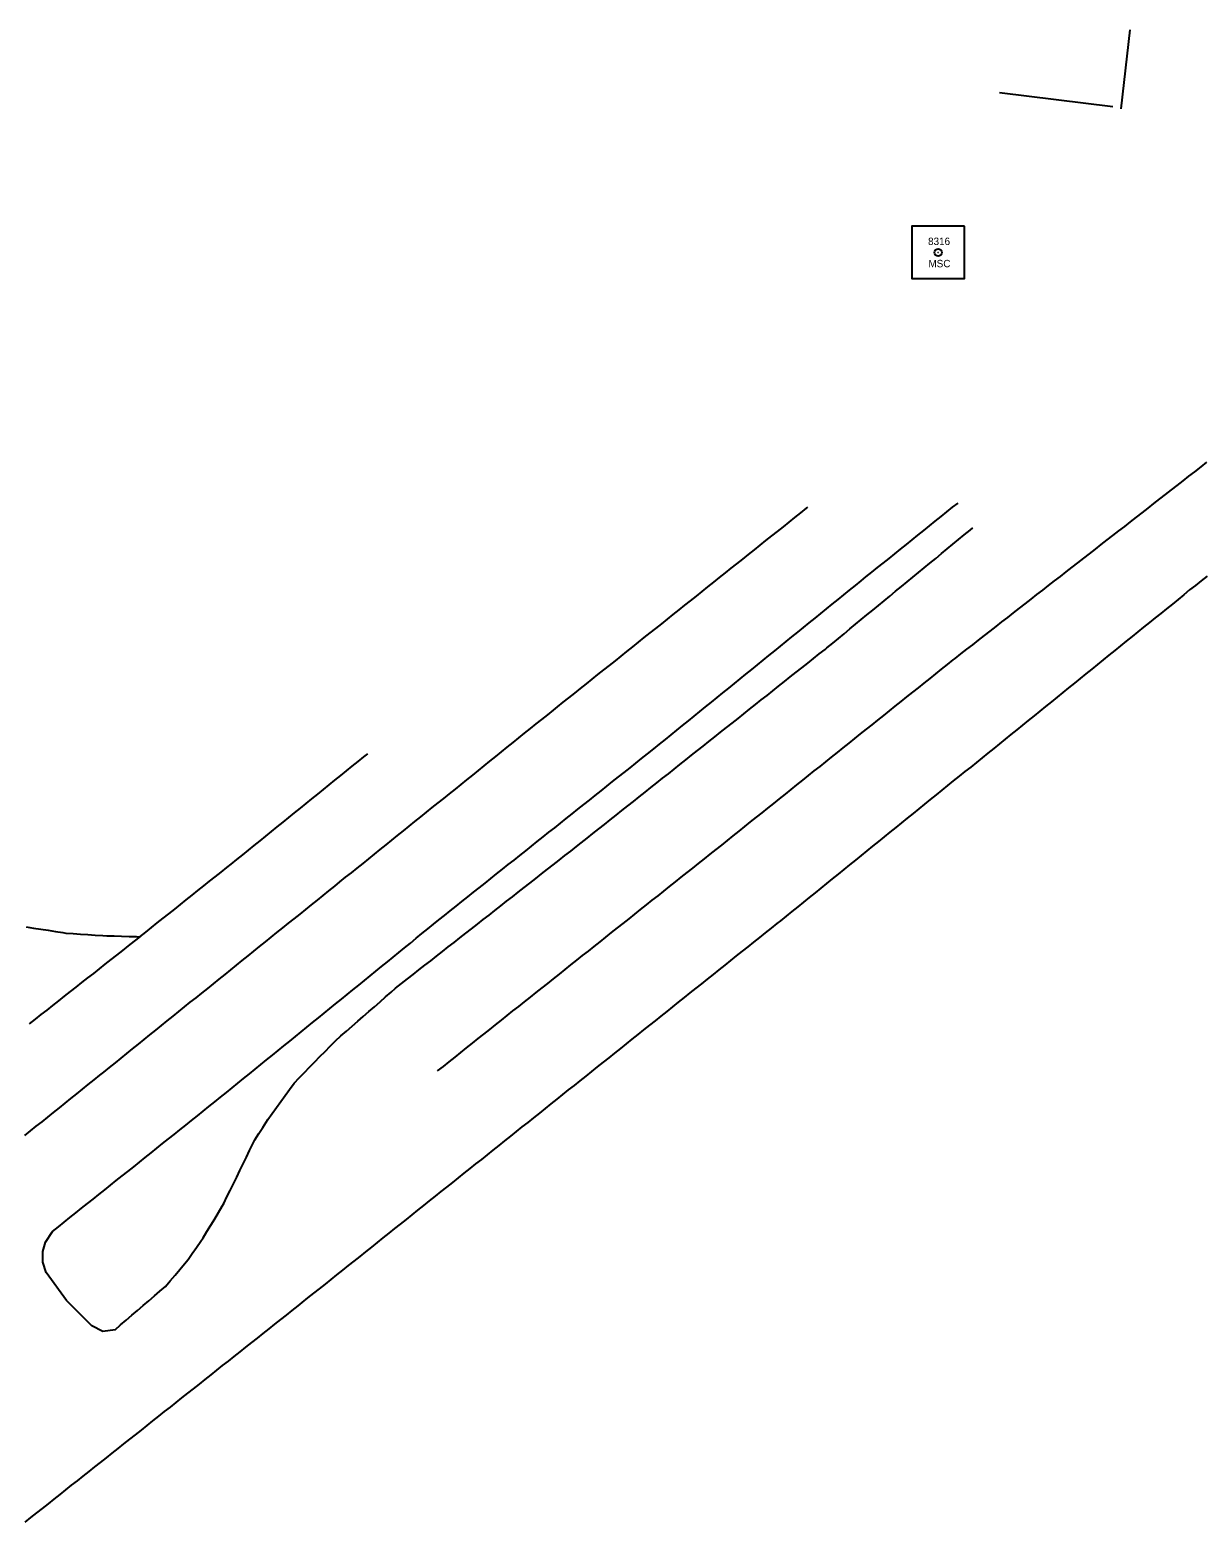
# Model space of a CAD drawing. Extents: x 205929 to 2357175, y -1785700 to 846739.
# Drawn here: x 2022787.1 to 2022945.3, y 806798.9 to 807000.3 of the extents above; entities that cross this region are included whole.
import ezdxf

# ---------------------------------------------------------------- set-up
doc = ezdxf.new("R2010")
doc.units = 0
for name, color, linetype in [('RD_HC_Survey', 7, 'Continuous'), ('RD_HC_txCode', 7, 'Continuous'), ('RD_Sketch1', 7, 'Continuous'), ('RD_SMD_Locator', 7, 'Continuous')]:
    doc.layers.add(name, color=color, linetype=linetype)

msp = doc.modelspace()

# ---------------------------------------------------------------- linework, layer by layer
at = {"layer": 'RD_HC_Survey'}
msp.add_lwpolyline([(2022913.2, 806973.76), (2022906.13, 806973.76), (2022906.13, 806966.69), (2022913.2, 806966.69)], close=True, dxfattribs=at)
msp.add_circle((2022909.67, 806970.22), 0.5, dxfattribs=at)
at = {"layer": 'RD_Sketch1'}
for points in [[(2022935.52, 807000.26), (2022934.33, 806989.6)], [(2022917.94, 806991.81), (2022933.23, 806989.93)], [(2022842.12, 806859.77), (2022842.9, 806860.39), (2022843.68, 806861.01), (2022844.47, 806861.64), (2022845.25, 806862.26), (2022846.03, 806862.88), (2022846.81, 806863.5), (2022847.6, 806864.13), (2022848.38, 806864.75), (2022849.16, 806865.37), (2022849.95, 806865.99), (2022850.73, 806866.62), (2022851.51, 806867.24), (2022852.29, 806867.86), (2022853.08, 806868.48), (2022853.86, 806869.1), (2022854.64, 806869.73), (2022855.42, 806870.35), (2022856.21, 806870.97), (2022856.99, 806871.59), (2022857.77, 806872.22), (2022858.56, 806872.84), (2022859.34, 806873.46), (2022860.12, 806874.08), (2022860.9, 806874.71), (2022861.69, 806875.33), (2022862.47, 806875.95), (2022863.25, 806876.57), (2022864.04, 806877.19), (2022864.82, 806877.82), (2022865.6, 806878.44), (2022866.38, 806879.06), (2022867.17, 806879.68), (2022867.95, 806880.31), (2022868.73, 806880.93), (2022869.51, 806881.55), (2022870.3, 806882.17), (2022871.08, 806882.8), (2022871.86, 806883.42), (2022872.65, 806884.04), (2022873.43, 806884.66), (2022874.21, 806885.28), (2022874.99, 806885.91), (2022875.78, 806886.53), (2022876.56, 806887.15), (2022877.34, 806887.77), (2022878.12, 806888.4), (2022878.91, 806889.02), (2022879.69, 806889.64), (2022880.46, 806890.25), (2022881.24, 806890.88), (2022882.02, 806891.5), (2022882.8, 806892.13), (2022883.58, 806892.75), (2022884.36, 806893.37), (2022885.14, 806894), (2022885.92, 806894.62), (2022886.7, 806895.25), (2022887.49, 806895.87), (2022888.27, 806896.5), (2022889.05, 806897.12), (2022889.83, 806897.75), (2022890.61, 806898.37), (2022891.39, 806899), (2022892.17, 806899.62), (2022892.17, 806899.62), (2022892.95, 806900.25), (2022893.73, 806900.87), (2022894.51, 806901.5), (2022895.29, 806902.12), (2022896.07, 806902.74), (2022896.86, 806903.37), (2022897.64, 806903.99), (2022898.42, 806904.62), (2022899.2, 806905.24), (2022899.98, 806905.87), (2022900.76, 806906.49), (2022901.54, 806907.12), (2022902.32, 806907.74), (2022903.1, 806908.37), (2022903.88, 806908.99), (2022904.66, 806909.62), (2022905.45, 806910.24), (2022906.23, 806910.87), (2022907.01, 806911.49), (2022907.79, 806912.11), (2022908.57, 806912.74), (2022909.35, 806913.36), (2022910.13, 806913.99), (2022910.91, 806914.61), (2022911.69, 806915.24), (2022911.95, 806915.44), (2022912.74, 806916.06), (2022913.53, 806916.67), (2022914.32, 806917.29), (2022915.11, 806917.9), (2022915.9, 806918.52), (2022916.68, 806919.13), (2022917.47, 806919.74), (2022918.26, 806920.36), (2022919.05, 806920.97), (2022919.84, 806921.59), (2022920.63, 806922.2), (2022921.42, 806922.82), (2022922.21, 806923.43), (2022923, 806924.05), (2022923.79, 806924.66), (2022924.57, 806925.27), (2022925.36, 806925.89), (2022926.15, 806926.5), (2022926.94, 806927.12), (2022927.73, 806927.73), (2022928.52, 806928.35), (2022929.31, 806928.96), (2022930.1, 806929.57), (2022930.89, 806930.19), (2022931.68, 806930.8), (2022932.46, 806931.42), (2022933.25, 806932.03), (2022934.04, 806932.65), (2022934.83, 806933.26), (2022935.62, 806933.88), (2022936.41, 806934.49), (2022937.2, 806935.1), (2022937.99, 806935.72), (2022938.78, 806936.33), (2022939.57, 806936.95), (2022940.35, 806937.56), (2022941.14, 806938.18), (2022941.93, 806938.79), (2022941.93, 806938.79), (2022942.72, 806939.4), (2022943.51, 806940.02), (2022944.3, 806940.63), (2022945.13, 806941.28), (2022945.9, 806941.9)], [(2022892.04, 806935.85), (2022891.85, 806935.7), (2022891.07, 806935.08), (2022890.29, 806934.45), (2022889.51, 806933.83), (2022888.73, 806933.21), (2022887.94, 806932.58), (2022887.16, 806931.96), (2022886.38, 806931.34), (2022885.6, 806930.71), (2022884.82, 806930.09), (2022884.04, 806929.47), (2022883.25, 806928.84), (2022882.47, 806928.22), (2022881.69, 806927.6), (2022880.91, 806926.97), (2022880.13, 806926.35), (2022879.35, 806925.73), (2022878.56, 806925.1), (2022877.78, 806924.48), (2022877, 806923.86), (2022876.22, 806923.23), (2022875.44, 806922.61), (2022874.66, 806921.99), (2022873.87, 806921.36), (2022873.09, 806920.74), (2022872.31, 806920.11), (2022871.53, 806919.49), (2022870.75, 806918.87), (2022869.97, 806918.24), (2022869.18, 806917.62), (2022868.4, 806917), (2022867.62, 806916.37), (2022866.84, 806915.75), (2022866.06, 806915.13), (2022865.28, 806914.5), (2022864.49, 806913.88), (2022863.71, 806913.26), (2022862.93, 806912.63), (2022862.15, 806912.01), (2022861.37, 806911.39), (2022860.59, 806910.76), (2022859.8, 806910.14), (2022859.02, 806909.52), (2022858.24, 806908.89), (2022857.71, 806908.47), (2022856.93, 806907.84), (2022856.15, 806907.21), (2022856.15, 806907.21), (2022855.37, 806906.59), (2022854.6, 806905.96), (2022853.82, 806905.33), (2022853.04, 806904.71), (2022852.26, 806904.08), (2022851.48, 806903.45), (2022850.7, 806902.82), (2022849.92, 806902.2), (2022849.14, 806901.57), (2022848.36, 806900.94), (2022847.58, 806900.32), (2022846.81, 806899.69), (2022846.03, 806899.06), (2022845.25, 806898.44), (2022844.47, 806897.81), (2022843.69, 806897.18), (2022842.91, 806896.55), (2022842.13, 806895.93), (2022841.35, 806895.3), (2022840.57, 806894.67), (2022839.8, 806894.05), (2022839.02, 806893.42), (2022838.24, 806892.79), (2022837.46, 806892.17), (2022836.68, 806891.54), (2022835.9, 806890.91), (2022835.12, 806890.28), (2022834.34, 806889.66), (2022833.56, 806889.03), (2022832.79, 806888.4), (2022832.01, 806887.78), (2022831.23, 806887.15), (2022830.45, 806886.52), (2022829.67, 806885.9), (2022828.89, 806885.27), (2022828.19, 806884.7), (2022827.41, 806884.08), (2022826.63, 806883.45), (2022825.85, 806882.82), (2022825.07, 806882.19), (2022824.29, 806881.57), (2022823.51, 806880.94), (2022822.73, 806880.31), (2022821.96, 806879.69), (2022821.18, 806879.06), (2022820.4, 806878.43), (2022819.62, 806877.81), (2022818.84, 806877.18), (2022818.06, 806876.55), (2022817.28, 806875.92), (2022816.5, 806875.3), (2022815.72, 806874.67), (2022814.94, 806874.04), (2022814.17, 806873.42), (2022813.39, 806872.79), (2022812.61, 806872.16), (2022811.83, 806871.54), (2022811.05, 806870.91), (2022810.27, 806870.28), (2022809.49, 806869.65), (2022808.71, 806869.03), (2022807.93, 806868.4), (2022807.15, 806867.77), (2022806.38, 806867.15), (2022806.38, 806867.15), (2022805.6, 806866.52), (2022804.82, 806865.89), (2022804.04, 806865.27), (2022803.26, 806864.64), (2022802.48, 806864.01), (2022801.7, 806863.38), (2022800.92, 806862.76), (2022800.14, 806862.13), (2022799.36, 806861.5), (2022798.59, 806860.88), (2022797.81, 806860.25), (2022797.03, 806859.62), (2022796.49, 806859.19), (2022795.72, 806858.57), (2022794.94, 806857.94), (2022794.16, 806857.31), (2022793.38, 806856.69), (2022792.6, 806856.06), (2022791.82, 806855.43), (2022791.04, 806854.8), (2022790.26, 806854.18), (2022789.48, 806853.55), (2022788.71, 806852.92), (2022787.93, 806852.3), (2022787.15, 806851.67), (2022786.37, 806851.04)], [(2022790.17, 806838.11), (2022790.95, 806838.74), (2022791.73, 806839.36), (2022792.51, 806839.98), (2022793.29, 806840.61), (2022794.07, 806841.23), (2022794.86, 806841.86), (2022795.64, 806842.48), (2022796.42, 806843.1), (2022797.2, 806843.73), (2022797.98, 806844.35), (2022798.76, 806844.98), (2022799.54, 806845.6), (2022800.33, 806846.22), (2022801.11, 806846.85), (2022801.89, 806847.47), (2022802.67, 806848.1), (2022803.45, 806848.72), (2022804.23, 806849.34), (2022805.01, 806849.97), (2022805.8, 806850.59), (2022806.58, 806851.21), (2022807.36, 806851.84), (2022808.14, 806852.46), (2022808.92, 806853.09), (2022809.7, 806853.71), (2022810.49, 806854.33), (2022811.27, 806854.96), (2022812.05, 806855.58), (2022812.84, 806856.22), (2022813.62, 806856.85), (2022814.4, 806857.48), (2022815.17, 806858.11), (2022815.95, 806858.74), (2022816.72, 806859.37), (2022817.5, 806860), (2022818.28, 806860.63), (2022819.05, 806861.26), (2022819.83, 806861.9), (2022820.6, 806862.53), (2022821.38, 806863.16), (2022822.16, 806863.79), (2022822.93, 806864.42), (2022823.71, 806865.05), (2022824.48, 806865.68), (2022825.26, 806866.31), (2022826.03, 806866.94), (2022826.81, 806867.57), (2022827.59, 806868.2), (2022828.36, 806868.83), (2022829.14, 806869.46), (2022829.91, 806870.1), (2022830.69, 806870.73), (2022831.47, 806871.36), (2022832.24, 806871.99), (2022833.02, 806872.62), (2022833.79, 806873.25), (2022834.57, 806873.88), (2022835.35, 806874.51), (2022836.12, 806875.14), (2022836.9, 806875.77), (2022837.67, 806876.4), (2022838.45, 806877.03), (2022839.23, 806877.67), (2022840, 806878.3), (2022840, 806878.3), (2022840.78, 806878.93), (2022841.55, 806879.56), (2022842.27, 806880.14), (2022843.05, 806880.76), (2022843.83, 806881.38), (2022844.62, 806882.01), (2022845.4, 806882.63), (2022846.18, 806883.25), (2022846.96, 806883.88), (2022847.75, 806884.5), (2022848.53, 806885.12), (2022849.31, 806885.74), (2022850.09, 806886.37), (2022850.88, 806886.99), (2022851.66, 806887.61), (2022852.44, 806888.23), (2022853.22, 806888.86), (2022854.01, 806889.48), (2022854.79, 806890.1), (2022855.57, 806890.72), (2022856.35, 806891.35), (2022857.14, 806891.97), (2022857.92, 806892.59), (2022858.7, 806893.22), (2022859.48, 806893.84), (2022860.26, 806894.46), (2022861.05, 806895.08), (2022861.83, 806895.71), (2022862.61, 806896.33), (2022863.39, 806896.95), (2022864.18, 806897.57), (2022864.96, 806898.2), (2022865.74, 806898.82), (2022866.52, 806899.44), (2022867.31, 806900.06), (2022868.09, 806900.69), (2022868.87, 806901.31), (2022869.65, 806901.93), (2022870.44, 806902.56), (2022871.3, 806903.24), (2022872.07, 806903.87), (2022872.85, 806904.5), (2022873.63, 806905.13), (2022874.4, 806905.76), (2022875.18, 806906.39), (2022875.96, 806907.02), (2022876.73, 806907.65), (2022877.51, 806908.28), (2022878.29, 806908.9), (2022879.07, 806909.53), (2022879.84, 806910.16), (2022880.62, 806910.79), (2022881.4, 806911.42), (2022882.17, 806912.05), (2022882.95, 806912.68), (2022883.73, 806913.31), (2022884.5, 806913.94), (2022885.28, 806914.57), (2022886.06, 806915.2), (2022886.83, 806915.83), (2022887.61, 806916.46), (2022888.39, 806917.09), (2022889.17, 806917.72), (2022889.94, 806918.35), (2022889.94, 806918.35), (2022890.72, 806918.98), (2022891.5, 806919.61), (2022892.27, 806920.24), (2022893.05, 806920.87), (2022893.83, 806921.5), (2022894.6, 806922.13), (2022895.38, 806922.76), (2022896.16, 806923.39), (2022896.93, 806924.01), (2022897.71, 806924.64), (2022898.49, 806925.27), (2022899.27, 806925.9), (2022899.92, 806926.43), (2022900.7, 806927.06), (2022901.48, 806927.69), (2022902.26, 806928.31), (2022903.04, 806928.94), (2022903.82, 806929.56), (2022904.6, 806930.19), (2022905.38, 806930.82), (2022906.16, 806931.44), (2022906.94, 806932.07), (2022907.72, 806932.7), (2022908.5, 806933.32), (2022909.28, 806933.95), (2022910.06, 806934.57), (2022910.84, 806935.2), (2022911.62, 806935.83), (2022912.35, 806936.41)], [(2022798.59, 806824.85), (2022799.34, 806825.5), (2022800.1, 806826.15), (2022800.86, 806826.8), (2022801.62, 806827.45), (2022802.38, 806828.1), (2022803.14, 806828.75), (2022803.9, 806829.4), (2022804.66, 806830.05), (2022805.4, 806830.68), (2022806.04, 806831.45), (2022806.69, 806832.22), (2022807.33, 806832.98), (2022807.97, 806833.75), (2022808.45, 806834.31), (2022809.02, 806835.13), (2022809.59, 806835.95), (2022810.16, 806836.78), (2022810.49, 806837.25), (2022811, 806838.11), (2022811.52, 806838.97), (2022812.04, 806839.82), (2022812.55, 806840.68), (2022813.07, 806841.54), (2022813.26, 806841.86), (2022813.7, 806842.76), (2022814.13, 806843.65), (2022814.57, 806844.55), (2022815.01, 806845.45), (2022815.45, 806846.35), (2022815.89, 806847.25), (2022816.32, 806848.15), (2022816.76, 806849.05), (2022817.2, 806849.95), (2022817.45, 806850.47), (2022817.99, 806851.31), (2022818.53, 806852.15), (2022819.21, 806853.22), (2022819.8, 806854.03), (2022820.38, 806854.84), (2022820.97, 806855.65), (2022821.55, 806856.46), (2022822.14, 806857.27), (2022822.75, 806858.12), (2022823.45, 806858.83), (2022824.15, 806859.55), (2022824.85, 806860.26), (2022825.54, 806860.98), (2022826.24, 806861.7), (2022826.94, 806862.41), (2022827.64, 806863.13), (2022828.33, 806863.83), (2022829.08, 806864.49), (2022829.83, 806865.15), (2022830.58, 806865.81), (2022831.34, 806866.47), (2022832.09, 806867.13), (2022832.84, 806867.78), (2022833.59, 806868.44), (2022834.35, 806869.1), (2022835.1, 806869.76), (2022835.85, 806870.42), (2022836.46, 806870.95), (2022837.25, 806871.57), (2022838.04, 806872.18), (2022838.04, 806872.18), (2022838.82, 806872.8), (2022839.61, 806873.42), (2022840.4, 806874.03), (2022841.19, 806874.65), (2022841.97, 806875.27), (2022842.76, 806875.88), (2022843.55, 806876.5), (2022844.34, 806877.11), (2022845.12, 806877.73), (2022845.91, 806878.35), (2022846.7, 806878.96), (2022847.49, 806879.58), (2022848.27, 806880.2), (2022849.06, 806880.81), (2022849.85, 806881.43), (2022850.64, 806882.04), (2022851.42, 806882.66), (2022852.21, 806883.28), (2022853, 806883.89), (2022853.79, 806884.51), (2022854.57, 806885.13), (2022855.36, 806885.74), (2022856.15, 806886.36), (2022856.93, 806886.98), (2022857.72, 806887.59), (2022858.51, 806888.21), (2022859.3, 806888.82), (2022860.08, 806889.44), (2022860.87, 806890.06), (2022861.51, 806890.55), (2022862.29, 806891.18), (2022863.07, 806891.8), (2022863.86, 806892.42), (2022864.64, 806893.04), (2022865.42, 806893.66), (2022866.21, 806894.28), (2022866.99, 806894.91), (2022867.77, 806895.53), (2022868.56, 806896.15), (2022869.34, 806896.77), (2022870.12, 806897.39), (2022870.91, 806898.01), (2022871.69, 806898.64), (2022872.47, 806899.26), (2022873.26, 806899.88), (2022874.04, 806900.5), (2022874.82, 806901.12), (2022875.61, 806901.74), (2022876.39, 806902.37), (2022877.17, 806902.99), (2022877.96, 806903.61), (2022878.74, 806904.23), (2022879.52, 806904.85), (2022880.31, 806905.47), (2022881.09, 806906.1), (2022881.87, 806906.72), (2022882.66, 806907.34), (2022883.44, 806907.96), (2022884.22, 806908.58), (2022885.01, 806909.2), (2022885.79, 806909.83), (2022886.57, 806910.45), (2022887.36, 806911.07), (2022888.14, 806911.69), (2022888.14, 806911.69), (2022888.92, 806912.31), (2022889.71, 806912.93), (2022890.49, 806913.56), (2022891.27, 806914.18), (2022892.06, 806914.8), (2022892.84, 806915.42), (2022893.62, 806916.04), (2022894.41, 806916.66), (2022894.66, 806916.87), (2022895.43, 806917.5), (2022896.2, 806918.14), (2022896.98, 806918.77), (2022897.75, 806919.41), (2022898.52, 806920.04), (2022899.29, 806920.68), (2022900.06, 806921.32), (2022900.84, 806921.95), (2022901.61, 806922.59), (2022902.38, 806923.22), (2022903.15, 806923.86), (2022903.92, 806924.49), (2022904.7, 806925.13), (2022905.47, 806925.76), (2022906.24, 806926.4), (2022907.01, 806927.03), (2022907.78, 806927.67), (2022908.56, 806928.31), (2022909.33, 806928.94), (2022910.1, 806929.58), (2022910.87, 806930.21), (2022911.64, 806930.85), (2022912.42, 806931.48), (2022913.19, 806932.12), (2022913.96, 806932.75), (2022914.34, 806933.07)], [(2022945.94, 806926.55), (2022945.16, 806925.92), (2022944.38, 806925.29), (2022943.6, 806924.67), (2022942.83, 806924.04), (2022942.05, 806923.41), (2022941.27, 806922.78), (2022940.49, 806922.15), (2022939.72, 806921.52), (2022938.94, 806920.9), (2022938.16, 806920.27), (2022937.38, 806919.64), (2022936.6, 806919.01), (2022935.83, 806918.38), (2022935.05, 806917.75), (2022934.27, 806917.12), (2022933.49, 806916.5), (2022932.71, 806915.87), (2022931.94, 806915.24), (2022931.16, 806914.61), (2022930.38, 806913.98), (2022929.6, 806913.35), (2022928.83, 806912.73), (2022928.05, 806912.1), (2022927.27, 806911.47), (2022926.49, 806910.84), (2022925.71, 806910.21), (2022924.94, 806909.58), (2022924.16, 806908.95), (2022923.38, 806908.33), (2022922.6, 806907.7), (2022921.83, 806907.07), (2022921.05, 806906.44), (2022920.27, 806905.81), (2022919.49, 806905.18), (2022918.71, 806904.55), (2022917.94, 806903.93), (2022917.16, 806903.3), (2022916.38, 806902.67), (2022915.6, 806902.04), (2022914.83, 806901.41), (2022914.05, 806900.78), (2022913.27, 806900.16), (2022912.49, 806899.53), (2022911.71, 806898.9), (2022910.94, 806898.27), (2022910.16, 806897.64), (2022909.38, 806897.01), (2022908.6, 806896.38), (2022907.82, 806895.76), (2022907.05, 806895.13), (2022906.27, 806894.5), (2022905.49, 806893.87), (2022904.71, 806893.24), (2022903.94, 806892.61), (2022903.16, 806891.99), (2022902.38, 806891.36), (2022901.6, 806890.73), (2022900.82, 806890.1), (2022900.05, 806889.47), (2022899.27, 806888.84), (2022898.49, 806888.21), (2022897.71, 806887.59), (2022896.94, 806886.96), (2022896.16, 806886.33), (2022895.38, 806885.7), (2022894.6, 806885.07), (2022893.82, 806884.44), (2022893.05, 806883.82), (2022892.27, 806883.19), (2022891.49, 806882.56), (2022890.71, 806881.93), (2022889.94, 806881.3), (2022889.16, 806880.67), (2022888.38, 806880.04), (2022887.89, 806879.65), (2022887.11, 806879.03), (2022886.33, 806878.4), (2022885.55, 806877.78), (2022884.76, 806877.15), (2022883.98, 806876.53), (2022883.2, 806875.91), (2022882.42, 806875.28), (2022881.64, 806874.66), (2022880.86, 806874.04), (2022880.08, 806873.41), (2022879.29, 806872.79), (2022878.51, 806872.17), (2022877.73, 806871.54), (2022876.95, 806870.92), (2022876.17, 806870.29), (2022875.39, 806869.67), (2022874.6, 806869.05), (2022873.82, 806868.42), (2022873.04, 806867.8), (2022872.26, 806867.18), (2022871.48, 806866.55), (2022870.7, 806865.93), (2022869.91, 806865.31), (2022869.13, 806864.68), (2022868.35, 806864.06), (2022867.57, 806863.43), (2022866.79, 806862.81), (2022866.01, 806862.19), (2022865.22, 806861.56), (2022864.44, 806860.94), (2022863.66, 806860.32), (2022862.88, 806859.69), (2022862.1, 806859.07), (2022861.32, 806858.44), (2022860.53, 806857.82), (2022859.75, 806857.2), (2022858.97, 806856.57), (2022858.19, 806855.95), (2022857.41, 806855.33), (2022856.63, 806854.7), (2022855.85, 806854.08), (2022855.06, 806853.46), (2022854.28, 806852.83), (2022853.5, 806852.21), (2022852.72, 806851.58), (2022851.94, 806850.96), (2022851.16, 806850.34), (2022850.37, 806849.71), (2022849.59, 806849.09), (2022848.81, 806848.47), (2022848.03, 806847.84), (2022847.25, 806847.22), (2022846.47, 806846.6), (2022845.68, 806845.97), (2022844.9, 806845.35), (2022844.12, 806844.72), (2022843.34, 806844.1), (2022842.56, 806843.48), (2022841.78, 806842.85), (2022840.99, 806842.23), (2022840.21, 806841.61), (2022839.43, 806840.98), (2022838.65, 806840.36), (2022837.87, 806839.73), (2022837.09, 806839.11), (2022836.3, 806838.49), (2022835.52, 806837.86), (2022834.74, 806837.24), (2022833.96, 806836.62), (2022833.18, 806835.99), (2022832.4, 806835.37), (2022831.62, 806834.75), (2022830.83, 806834.12), (2022830.05, 806833.5), (2022829.27, 806832.87), (2022828.49, 806832.25), (2022827.71, 806831.63), (2022826.93, 806831), (2022826.14, 806830.38), (2022825.36, 806829.76), (2022824.58, 806829.13), (2022823.8, 806828.51), (2022823.26, 806828.07), (2022822.47, 806827.45), (2022821.69, 806826.83), (2022820.9, 806826.21), (2022820.12, 806825.59), (2022819.34, 806824.97), (2022818.55, 806824.35), (2022817.77, 806823.73), (2022816.99, 806823.11), (2022816.2, 806822.48), (2022815.42, 806821.86), (2022814.64, 806821.24), (2022813.85, 806820.62), (2022813.07, 806820), (2022812.28, 806819.38), (2022811.5, 806818.76), (2022810.72, 806818.14), (2022809.93, 806817.51), (2022809.15, 806816.89), (2022808.37, 806816.27), (2022807.58, 806815.65), (2022806.8, 806815.03), (2022806.02, 806814.41), (2022805.23, 806813.79), (2022804.45, 806813.17), (2022803.66, 806812.54), (2022802.88, 806811.92), (2022802.1, 806811.3), (2022801.31, 806810.68), (2022800.53, 806810.06), (2022799.75, 806809.44), (2022798.96, 806808.82), (2022798.18, 806808.2), (2022797.4, 806807.57), (2022796.61, 806806.95), (2022795.83, 806806.33), (2022795.05, 806805.71), (2022794.26, 806805.09), (2022793.48, 806804.47), (2022792.69, 806803.85), (2022791.91, 806803.23), (2022791.13, 806802.6), (2022790.34, 806801.98), (2022789.56, 806801.36), (2022788.78, 806800.74), (2022787.99, 806800.12), (2022787.21, 806799.5), (2022786.43, 806798.88)], [(2022801.96, 806877.88), (2022802.74, 806878.5), (2022803.52, 806879.12), (2022804.3, 806879.75), (2022805.08, 806880.37), (2022805.87, 806880.99), (2022806.65, 806881.62), (2022807.43, 806882.24), (2022808.21, 806882.86), (2022808.99, 806883.49), (2022809.78, 806884.11), (2022810.56, 806884.73), (2022811.34, 806885.36), (2022812.12, 806885.98), (2022812.9, 806886.6), (2022813.69, 806887.23), (2022814.27, 806887.69), (2022815.05, 806888.32), (2022815.83, 806888.95), (2022816.6, 806889.58), (2022817.38, 806890.21), (2022818.16, 806890.83), (2022818.94, 806891.46), (2022819.72, 806892.09), (2022820.49, 806892.72), (2022821.27, 806893.35), (2022822.05, 806893.98), (2022822.83, 806894.6), (2022823.61, 806895.23), (2022824.38, 806895.86), (2022825.16, 806896.49), (2022825.94, 806897.12), (2022826.72, 806897.74), (2022827.49, 806898.37), (2022828.27, 806899), (2022829.05, 806899.63), (2022829.83, 806900.26), (2022830.61, 806900.88), (2022831.38, 806901.51), (2022832.16, 806902.14), (2022832.7, 806902.57)], [(2022786.59, 806879.21), (2022787.58, 806879.05), (2022788.57, 806878.9), (2022789.55, 806878.75), (2022790.54, 806878.59), (2022791.53, 806878.44), (2022791.94, 806878.37), (2022792.93, 806878.31), (2022793.93, 806878.24), (2022794.93, 806878.17), (2022795.93, 806878.11), (2022796.93, 806878.04), (2022797.49, 806878), (2022798.49, 806877.98), (2022799.48, 806877.95), (2022800.48, 806877.92), (2022801.48, 806877.89), (2022801.96, 806877.88), (2022801.17, 806877.26), (2022800.38, 806876.64), (2022799.6, 806876.03), (2022798.81, 806875.41), (2022798.03, 806874.79), (2022797.24, 806874.17), (2022796.45, 806873.55), (2022795.67, 806872.94), (2022794.88, 806872.32), (2022794.09, 806871.7), (2022793.31, 806871.08), (2022792.52, 806870.47), (2022791.74, 806869.85), (2022790.95, 806869.23), (2022790.16, 806868.61), (2022789.38, 806867.99), (2022788.59, 806867.38), (2022787.8, 806866.76), (2022787.02, 806866.14)], [(2022798.59, 806824.85), (2022796.93, 806824.61), (2022795.48, 806825.39), (2022792.04, 806828.8), (2022789.29, 806832.58), (2022788.87, 806833.97), (2022788.86, 806835.41), (2022789.21, 806836.65), (2022790.17, 806838.11)]]:
    msp.add_lwpolyline(points, dxfattribs=at)
at = {"layer": 'RD_SMD_Locator'}
msp.add_circle((2022909.67, 806970.22), 0.001, dxfattribs=at)

# ---------------------------------------------------------------- texts
at = {"layer": 'RD_HC_txCode'}
for s, p in [('8316', (2022908.3, 806971.22)), ('MSC', (2022908.35, 806968.22))]:
    msp.add_text(s, height=1, dxfattribs=at).set_placement(p)

doc.saveas('drawing.dxf')
